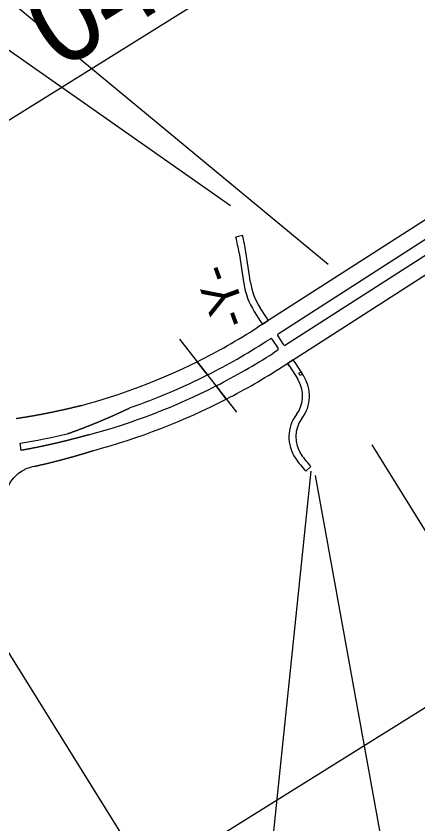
# Model space of a CAD drawing. Extents: x 2038094 to 2053858, y 751760 to 764312.
# Drawn here: x 2046307 to 2046894, y 757655 to 758834 of the extents above; entities that cross this region are included whole.
import ezdxf

# ---------------------------------------------------------------- set-up
doc = ezdxf.new("R2010")
doc.units = 0
for name, color, linetype in [('Default', 7, 'Continuous'), ('Old_Level_14', 7, 'Continuous'), ('Prop Shade Light', 7, 'Continuous'), ('Scratch_Level_1', 7, 'Continuous'), ('Sheet Data Field CELL', 7, 'Continuous')]:
    doc.layers.add(name, color=color, linetype=linetype)

msp = doc.modelspace()

# ---------------------------------------------------------------- linework, layer by layer
at = {"layer": 'Default'}
for p, q in [((2046545.4, 758362.6), (2046628.7, 758255.8)), ((2046595.2, 758298.9), (2046595.2, 758298.9)), ((2046595.2, 758298.9), (2046595.2, 758298.9))]:
    msp.add_line(p, q, dxfattribs=at)
at = {"layer": 'Old_Level_14'}
for points in [[(2046763, 758471.6), (2046248.1, 758896.8), (2045732.1, 758575.3)], [(2046620.1, 758557.1), (2046270.1, 758802), (2045682.1, 758435.8)], [(2046826.6, 758207.9), (2046916.9, 758063.2), (2047239.3, 758264)], [(2046737.4, 758169.4), (2046678.7, 757601.6), (2045930.3, 757135.4)], [(2046743.8, 758163.4), (2046879, 757418.7), (2046051.1, 756903.1)]]:
    msp.add_lwpolyline(points, dxfattribs=at)
at = {"layer": 'Prop Shade Light'}
for p, q in [((2047171.9, 758708.2), (2046658.7, 758379)), ((2046689.7, 758370.3), (2047184.9, 758688)), ((2046999.6, 758545.4), (2046700.5, 758353.5)), ((2046695.4, 758321.8), (2047012.6, 758525.2)), ((2046637.7, 758513.7), (2046627.9, 758511.3)), ((2046632.5, 758488.3), (2046639.5, 758443.4)), ((2046649.3, 758445), (2046642.4, 758489.8)), ((2046672.5, 758393.8), (2046663.2, 758408.3)), ((2046664.1, 758388.4), (2046666.8, 758384.2)), ((2046664.1, 758388.4), (2046666.8, 758384.2)), ((2046666.8, 758384.2), (2046675.2, 758389.6)), ((2046672.5, 758393.8), (2046675.2, 758389.6)), ((2046675.2, 758389.6), (2046672.5, 758393.8)), ((2046698, 758354), (2046689.1, 758367.9)), ((2046671.7, 758358.8), (2046678.3, 758363)), ((2046680.7, 758362.5), (2046689.6, 758348.6)), ((2046689.1, 758346.2), (2046682.5, 758342)), ((2046586.3, 758310.1), (2046571.2, 758329.4)), ((2046571.2, 758329.4), (2046586.3, 758310.1)), ((2046711.9, 758332.3), (2046703.5, 758326.9)), ((2046714.7, 758328.1), (2046711.9, 758332.3)), ((2046714.7, 758328.1), (2046711.9, 758332.3)), ((2046706.2, 758322.8), (2046703.5, 758326.9)), ((2046703.5, 758326.9), (2046706.2, 758322.8)), ((2046706.2, 758322.8), (2046718.4, 758303.8)), ((2046723.3, 758314.7), (2046714.7, 758328.1)), ((2046726.8, 758309.2), (2046723.3, 758314.7)), ((2046613.9, 758274.8), (2046598.9, 758294.1)), ((2046598.9, 758294.1), (2046613.9, 758274.8)), ((2046314, 758200), (2046312.3, 758210.4)), ((2046314, 758200), (2046312.3, 758210.4)), ((2046418.7, 758199.5), (2046418.7, 758199.5)), ((2046730.3, 758169.5), (2046737.6, 758176.4)), ((2046319.1, 758172), (2046318.6, 758171.9)), ((2046319.1, 758172), (2046318.6, 758171.9))]:
    msp.add_line(p, q, dxfattribs=at)
for points in [[(2046654.8, 758402.9), (2046654.8, 758402.9), (2046664.1, 758388.4)], [(2046723.3, 758314.7), (2046725.4, 758311.3), (2046722, 758309.2), (2046719.9, 758312.6), (2046723.3, 758314.7)], [(2046291.3, 758121.3), (2046291.2, 758122.5), (2046290.9, 758125.8), (2046290.8, 758130.1), (2046291, 758133.2), (2046291.8, 758138.8), (2046293.1, 758143), (2046293.8, 758144.8), (2046295.7, 758148.8), (2046297.9, 758152.8), (2046300.2, 758156.4), (2046303, 758159.9), (2046305.1, 758162), (2046307.5, 758164.2), (2046309.6, 758166), (2046312.7, 758168.5), (2046315.5, 758170.1), (2046319.1, 758172)]]:
    msp.add_lwpolyline(points, dxfattribs=at)
for centre, radius, start, end in [((2046341, 758443), 295, 8.8387, 13.4036), ((2046341, 758443), 305, 8.8387, 13.4036), ((2046743.2, 758459.6), 105, 188.8387, 212.6647), ((2046743.2, 758459.6), 95, 188.8387, 212.6814), ((2046164.1, 759150), 916, 296.388, 302.6814), ((2046690.6, 758368.9), 1.75, 122.6814, 212.6814), ((2046164.1, 759150), 940, 296.6881, 302.6814), ((2046679.2, 758361.6), 1.75, 32.6814, 122.6814), ((2046699.5, 758355), 1.75, 212.6814, 302.6814), ((2046164.1, 759150), 960, 296.9266, 302.6814), ((2046688.2, 758347.7), 1.75, 302.6814, 32.6814), ((2046164.1, 759150), 916, 284.9956, 296.388), ((2046164.1, 759150), 984, 297.1997, 302.6814), ((2046164.1, 759150), 940, 289.2174, 296.6881), ((2046680.5, 758279.5), 55, 323.1156, 32.6814), ((2046164.1, 759150), 960, 284.9956, 296.9266), ((2046680.5, 758279.5), 45, 323.1156, 32.6814), ((2046164.1, 759150), 984, 284.9956, 297.1997), ((2046760.5, 758219.5), 55, 143.1156, 214.5162), ((2046760.5, 758219.5), 45, 143.1156, 214.5162), ((2046152.4, 759198.6), 1001, 279.1966, 283.2073), ((2046847, 758279), 160, 214.5162, 223.1771), ((2046847, 758279), 150, 214.5162, 223.1771), ((2046350.9, 758096.8), 81.7, 102.2238, 113.2762)]:
    msp.add_arc(centre, radius, start, end, dxfattribs=at)
for points in [[(2046385.5, 758261.3), (2046385.3, 758261.3), (2046384.7, 758261.1), (2046384, 758261), (2046383.4, 758260.9), (2046382.8, 758260.7), (2046382.1, 758260.6), (2046381.5, 758260.4), (2046380.9, 758260.3), (2046380.2, 758260.1), (2046379.6, 758260), (2046379, 758259.8), (2046378.3, 758259.7), (2046377.7, 758259.5), (2046377.1, 758259.4), (2046376.4, 758259.2), (2046375.8, 758259.1), (2046375.1, 758259), (2046374.5, 758258.8), (2046373.9, 758258.7), (2046373.2, 758258.5), (2046372.6, 758258.4), (2046372, 758258.3), (2046371.3, 758258.1), (2046370.7, 758258), (2046370.1, 758257.8), (2046369.8, 758257.8)], [(2046401.1, 758265.2), (2046399.9, 758264.9), (2046399.2, 758264.7), (2046398.6, 758264.5), (2046398, 758264.4), (2046397.3, 758264.2), (2046396.7, 758264.1), (2046396.1, 758263.9), (2046395.4, 758263.7), (2046394.8, 758263.6), (2046394.2, 758263.4), (2046393.5, 758263.3), (2046392.9, 758263.1), (2046392.3, 758263), (2046391.6, 758262.8), (2046391, 758262.7), (2046390.4, 758262.5), (2046389.7, 758262.4), (2046389.1, 758262.2), (2046388.5, 758262.1), (2046387.8, 758261.9), (2046387.2, 758261.7), (2046386.6, 758261.6), (2046385.9, 758261.4), (2046385.5, 758261.3)], [(2046458.5, 758255.3), (2046458.9, 758255.5), (2046459.5, 758255.8), (2046460.1, 758256.1), (2046460.7, 758256.4), (2046461.3, 758256.6), (2046461.9, 758256.9), (2046462.6, 758257.2), (2046463.2, 758257.5), (2046463.8, 758257.8), (2046464.4, 758258.1), (2046465, 758258.3), (2046465.6, 758258.6), (2046466.2, 758258.9), (2046466.8, 758259.2), (2046467.4, 758259.5), (2046468.1, 758259.8), (2046468.7, 758260.1), (2046469.3, 758260.3), (2046469.9, 758260.6), (2046470.5, 758260.9), (2046471.1, 758261.2), (2046471.7, 758261.5), (2046472.3, 758261.8), (2046473.5, 758262.4)], [(2046322.4, 758248.7), (2046322, 758248.6), (2046321.4, 758248.5), (2046320.7, 758248.4), (2046320.1, 758248.3), (2046319.4, 758248.2), (2046318.8, 758248.1), (2046318.2, 758248), (2046317.5, 758247.9), (2046316.9, 758247.8), (2046316.2, 758247.7), (2046315.6, 758247.6), (2046314.9, 758247.5), (2046314.3, 758247.4), (2046313.6, 758247.3), (2046313, 758247.2), (2046312.4, 758247.1), (2046311.7, 758247), (2046311.1, 758246.9), (2046310.4, 758246.8), (2046309.8, 758246.7), (2046309.1, 758246.6), (2046308.5, 758246.5), (2046307.8, 758246.4), (2046307.2, 758246.3), (2046306.6, 758246.2)], [(2046338.3, 758251.5), (2046338.1, 758251.4), (2046337.4, 758251.3), (2046336.8, 758251.2), (2046336.1, 758251.1), (2046335.5, 758250.9), (2046334.9, 758250.8), (2046334.2, 758250.7), (2046333.6, 758250.6), (2046332.9, 758250.5), (2046332.3, 758250.4), (2046331.7, 758250.3), (2046331, 758250.1), (2046330.4, 758250), (2046329.7, 758249.9), (2046329.1, 758249.8), (2046328.4, 758249.7), (2046327.8, 758249.6), (2046327.2, 758249.5), (2046326.5, 758249.4), (2046325.9, 758249.3), (2046325.2, 758249.2), (2046324.6, 758249), (2046323.9, 758248.9), (2046323.3, 758248.8), (2046322.7, 758248.7), (2046322.4, 758248.7)], [(2046354.1, 758254.5), (2046353.4, 758254.4), (2046352.8, 758254.2), (2046352.2, 758254.1), (2046351.5, 758254), (2046350.9, 758253.9), (2046350.2, 758253.7), (2046349.6, 758253.6), (2046349, 758253.5), (2046348.3, 758253.4), (2046347.7, 758253.2), (2046347, 758253.1), (2046346.4, 758253), (2046345.8, 758252.9), (2046345.1, 758252.7), (2046344.5, 758252.6), (2046343.8, 758252.5), (2046343.2, 758252.4), (2046342.6, 758252.2), (2046341.9, 758252.1), (2046341.3, 758252), (2046340.6, 758251.9), (2046340, 758251.8), (2046339.4, 758251.7), (2046338.7, 758251.5), (2046338.3, 758251.5)], [(2046369.8, 758257.8), (2046369.4, 758257.7), (2046368.8, 758257.6), (2046368.1, 758257.4), (2046367.5, 758257.3), (2046366.9, 758257.1), (2046366.2, 758257), (2046365.6, 758256.9), (2046364.9, 758256.7), (2046364.3, 758256.6), (2046363.7, 758256.5), (2046363, 758256.3), (2046362.4, 758256.2), (2046361.8, 758256.1), (2046361.1, 758255.9), (2046360.5, 758255.8), (2046359.8, 758255.7), (2046359.2, 758255.5), (2046358.6, 758255.4), (2046357.9, 758255.3), (2046357.3, 758255.1), (2046356.6, 758255), (2046356, 758254.9), (2046355.4, 758254.7), (2046354.7, 758254.6), (2046354.1, 758254.5)], [(2046427.9, 758242), (2046428.6, 758242.3), (2046429.2, 758242.6), (2046429.8, 758242.8), (2046430.4, 758243.1), (2046431.1, 758243.3), (2046431.7, 758243.6), (2046432.3, 758243.9), (2046432.9, 758244.1), (2046433.6, 758244.4), (2046434.2, 758244.6), (2046434.8, 758244.9), (2046435.4, 758245.2), (2046436, 758245.4), (2046436.7, 758245.7), (2046437.3, 758246), (2046437.9, 758246.2), (2046438.5, 758246.5), (2046439.1, 758246.8), (2046439.8, 758247), (2046440.4, 758247.3), (2046441, 758247.6), (2046441.6, 758247.8), (2046442.2, 758248.1), (2046442.9, 758248.4), (2046443.3, 758248.5)], [(2046443.3, 758248.5), (2046443.5, 758248.6), (2046444.1, 758248.9), (2046444.7, 758249.2), (2046445.3, 758249.5), (2046446, 758249.7), (2046446.6, 758250), (2046447.2, 758250.3), (2046447.8, 758250.5), (2046448.4, 758250.8), (2046449, 758251.1), (2046449.7, 758251.4), (2046450.3, 758251.6), (2046450.9, 758251.9), (2046451.5, 758252.2), (2046452.1, 758252.5), (2046452.7, 758252.7), (2046453.4, 758253), (2046454, 758253.3), (2046454.6, 758253.6), (2046455.2, 758253.8), (2046455.8, 758254.1), (2046456.4, 758254.4), (2046457, 758254.7), (2046457.7, 758255), (2046458.3, 758255.2), (2046458.5, 758255.3)], [(2046396.8, 758229.8), (2046397, 758229.9), (2046397.7, 758230.1), (2046398.3, 758230.3), (2046398.9, 758230.6), (2046399.6, 758230.8), (2046400.2, 758231.1), (2046400.8, 758231.3), (2046401.5, 758231.5), (2046402.1, 758231.8), (2046402.8, 758232), (2046403.4, 758232.3), (2046404, 758232.5), (2046404.7, 758232.7), (2046405.3, 758233), (2046405.9, 758233.2), (2046406.6, 758233.5), (2046407.2, 758233.7), (2046407.8, 758234), (2046408.4, 758234.2), (2046409.1, 758234.5), (2046409.7, 758234.7), (2046410.3, 758235), (2046411, 758235.2), (2046411.6, 758235.4), (2046412.2, 758235.7), (2046412.4, 758235.8)], [(2046412.4, 758235.8), (2046412.9, 758235.9), (2046413.5, 758236.2), (2046414.1, 758236.4), (2046414.8, 758236.7), (2046415.4, 758236.9), (2046416, 758237.2), (2046416.6, 758237.4), (2046417.3, 758237.7), (2046417.9, 758237.9), (2046418.5, 758238.2), (2046419.2, 758238.4), (2046419.8, 758238.7), (2046420.4, 758239), (2046421, 758239.2), (2046421.7, 758239.5), (2046422.3, 758239.7), (2046422.9, 758240), (2046423.6, 758240.2), (2046424.2, 758240.5), (2046424.8, 758240.7), (2046425.4, 758241), (2046426.1, 758241.3), (2046426.7, 758241.5), (2046427.3, 758241.8), (2046427.9, 758242)], [(2046381.1, 758224.1), (2046381.7, 758224.3), (2046382.3, 758224.5), (2046383, 758224.7), (2046383.6, 758225), (2046384.3, 758225.2), (2046384.9, 758225.4), (2046385.5, 758225.7), (2046386.2, 758225.9), (2046386.8, 758226.1), (2046387.5, 758226.3), (2046388.1, 758226.6), (2046388.7, 758226.8), (2046389.4, 758227), (2046390, 758227.3), (2046390.7, 758227.5), (2046391.3, 758227.7), (2046391.9, 758228), (2046392.6, 758228.2), (2046393.2, 758228.4), (2046393.9, 758228.7), (2046394.5, 758228.9), (2046395.1, 758229.2), (2046395.8, 758229.4), (2046396.4, 758229.6), (2046396.8, 758229.8)], [(2046380, 758214), (2046379.5, 758213.9), (2046378.9, 758213.7), (2046378.2, 758213.6), (2046377.5, 758213.4), (2046376.9, 758213.2), (2046376.2, 758213.1), (2046375.5, 758212.9), (2046374.9, 758212.8), (2046374.2, 758212.6), (2046373.5, 758212.4), (2046372.9, 758212.3), (2046372.2, 758212.1), (2046371.6, 758212), (2046370.9, 758211.8), (2046370.2, 758211.6), (2046369.6, 758211.5), (2046368.9, 758211.3), (2046368.2, 758211.2), (2046367.6, 758211), (2046366.9, 758210.9), (2046366.2, 758210.7), (2046365.6, 758210.5), (2046364.9, 758210.4), (2046364.2, 758210.2), (2046363.6, 758210.1)], [(2046396.3, 758218.2), (2046396.1, 758218.1), (2046395.4, 758218), (2046394.7, 758217.8), (2046394.1, 758217.6), (2046393.4, 758217.4), (2046392.8, 758217.3), (2046392.1, 758217.1), (2046391.4, 758216.9), (2046390.8, 758216.7), (2046390.1, 758216.6), (2046389.4, 758216.4), (2046388.8, 758216.2), (2046388.1, 758216.1), (2046387.5, 758215.9), (2046386.8, 758215.7), (2046386.1, 758215.6), (2046385.5, 758215.4), (2046384.8, 758215.2), (2046384.2, 758215.1), (2046383.5, 758214.9), (2046382.8, 758214.7), (2046382.2, 758214.6), (2046381.5, 758214.4), (2046380.8, 758214.2), (2046380.2, 758214.1), (2046380, 758214)], [(2046412.5, 758222.7), (2046411.2, 758222.3), (2046410.5, 758222.1), (2046409.9, 758221.9), (2046409.2, 758221.7), (2046408.6, 758221.6), (2046407.9, 758221.4), (2046407.3, 758221.2), (2046406.6, 758221), (2046405.9, 758220.8), (2046405.3, 758220.6), (2046404.6, 758220.5), (2046404, 758220.3), (2046403.3, 758220.1), (2046402.7, 758219.9), (2046402, 758219.7), (2046401.3, 758219.6), (2046400.7, 758219.4), (2046400, 758219.2), (2046399.4, 758219), (2046398.7, 758218.8), (2046398, 758218.7), (2046397.4, 758218.5), (2046396.7, 758218.3), (2046396.3, 758218.2)], [(2046330.6, 758203.1), (2046330.2, 758203), (2046329.5, 758202.8), (2046328.8, 758202.7), (2046328.2, 758202.6), (2046327.5, 758202.4), (2046326.8, 758202.3), (2046326.1, 758202.2), (2046325.5, 758202.1), (2046324.8, 758201.9), (2046324.1, 758201.8), (2046323.5, 758201.7), (2046322.8, 758201.6), (2046322.1, 758201.4), (2046321.4, 758201.3), (2046320.8, 758201.2), (2046320.1, 758201.1), (2046319.4, 758200.9), (2046318.7, 758200.8), (2046318.1, 758200.7), (2046317.4, 758200.6), (2046316.7, 758200.4), (2046316.1, 758200.3), (2046315.4, 758200.2), (2046314.7, 758200.1), (2046314, 758200)], [(2046347.1, 758206.4), (2046346.9, 758206.4), (2046346.2, 758206.2), (2046345.6, 758206.1), (2046344.9, 758206), (2046344.2, 758205.8), (2046343.6, 758205.7), (2046342.9, 758205.5), (2046342.2, 758205.4), (2046341.6, 758205.3), (2046340.9, 758205.1), (2046340.2, 758205), (2046339.5, 758204.8), (2046338.9, 758204.7), (2046338.2, 758204.6), (2046337.5, 758204.4), (2046336.9, 758204.3), (2046336.2, 758204.2), (2046335.5, 758204), (2046334.9, 758203.9), (2046334.2, 758203.8), (2046333.5, 758203.6), (2046332.8, 758203.5), (2046332.2, 758203.4), (2046331.5, 758203.2), (2046330.8, 758203.1), (2046330.6, 758203.1)], [(2046363.6, 758210.1), (2046362.9, 758209.9), (2046362.2, 758209.8), (2046361.6, 758209.6), (2046360.9, 758209.5), (2046360.2, 758209.3), (2046359.6, 758209.2), (2046358.9, 758209), (2046358.2, 758208.9), (2046357.6, 758208.7), (2046356.9, 758208.6), (2046356.2, 758208.4), (2046355.6, 758208.3), (2046354.9, 758208.1), (2046354.2, 758208), (2046353.6, 758207.8), (2046352.9, 758207.7), (2046352.2, 758207.5), (2046351.6, 758207.4), (2046350.9, 758207.2), (2046350.2, 758207.1), (2046349.6, 758207), (2046348.9, 758206.8), (2046348.2, 758206.7), (2046347.6, 758206.5), (2046347.1, 758206.4)], [(2046404.7, 758195.2), (2046405.1, 758195.3), (2046405.6, 758195.5), (2046406.2, 758195.6), (2046406.8, 758195.8), (2046407.3, 758196), (2046407.9, 758196.2), (2046408.5, 758196.3), (2046409.1, 758196.5), (2046409.6, 758196.7), (2046410.2, 758196.8), (2046410.8, 758197), (2046411.3, 758197.2), (2046411.9, 758197.4), (2046412.5, 758197.5), (2046413, 758197.7), (2046413.6, 758197.9), (2046414.2, 758198.1), (2046414.7, 758198.2), (2046415.3, 758198.4), (2046415.9, 758198.6), (2046416.5, 758198.8), (2046417, 758199), (2046417.6, 758199.1), (2046418.7, 758199.5)], [(2046376.4, 758187.2), (2046377, 758187.4), (2046377.6, 758187.5), (2046378.1, 758187.7), (2046378.7, 758187.8), (2046379.3, 758188), (2046379.9, 758188.1), (2046380.4, 758188.3), (2046381, 758188.4), (2046381.6, 758188.6), (2046382.2, 758188.8), (2046382.7, 758188.9), (2046383.3, 758189.1), (2046383.9, 758189.2), (2046384.5, 758189.4), (2046385, 758189.5), (2046385.6, 758189.7), (2046386.2, 758189.9), (2046386.8, 758190), (2046387.3, 758190.2), (2046387.9, 758190.3), (2046388.5, 758190.5), (2046389, 758190.7), (2046389.6, 758190.8), (2046390.2, 758191), (2046390.6, 758191.1)], [(2046390.6, 758191.1), (2046390.8, 758191.1), (2046391.3, 758191.3), (2046391.9, 758191.5), (2046392.5, 758191.6), (2046393.1, 758191.8), (2046393.6, 758192), (2046394.2, 758192.1), (2046394.8, 758192.3), (2046395.3, 758192.5), (2046395.9, 758192.6), (2046396.5, 758192.8), (2046397.1, 758192.9), (2046397.6, 758193.1), (2046398.2, 758193.3), (2046398.8, 758193.4), (2046399.3, 758193.6), (2046399.9, 758193.8), (2046400.5, 758193.9), (2046401.1, 758194.1), (2046401.6, 758194.3), (2046402.2, 758194.5), (2046402.8, 758194.6), (2046403.3, 758194.8), (2046403.9, 758195), (2046404.5, 758195.1), (2046404.7, 758195.2)], [(2046333.6, 758176.7), (2046334.2, 758176.9), (2046334.7, 758177), (2046335.3, 758177.1), (2046335.9, 758177.2), (2046336.5, 758177.4), (2046337.1, 758177.5), (2046337.6, 758177.6), (2046338.2, 758177.8), (2046338.8, 758177.9), (2046339.4, 758178), (2046340, 758178.2), (2046340.6, 758178.3), (2046341.1, 758178.4), (2046341.7, 758178.6), (2046342.3, 758178.7), (2046342.9, 758178.8), (2046343.5, 758179), (2046344, 758179.1), (2046344.6, 758179.2), (2046345.2, 758179.4), (2046345.8, 758179.5), (2046346.4, 758179.6), (2046346.9, 758179.8), (2046347.5, 758179.9), (2046347.9, 758180)], [(2046347.9, 758180), (2046348.1, 758180.1), (2046348.7, 758180.2), (2046349.3, 758180.3), (2046349.8, 758180.5), (2046350.4, 758180.6), (2046351, 758180.8), (2046351.6, 758180.9), (2046352.2, 758181), (2046352.7, 758181.2), (2046353.3, 758181.3), (2046353.9, 758181.5), (2046354.5, 758181.6), (2046355.1, 758181.7), (2046355.6, 758181.9), (2046356.2, 758182), (2046356.8, 758182.2), (2046357.4, 758182.3), (2046357.9, 758182.4), (2046358.5, 758182.6), (2046359.1, 758182.7), (2046359.7, 758182.9), (2046360.3, 758183), (2046360.8, 758183.2), (2046361.4, 758183.3), (2046362, 758183.5), (2046362.2, 758183.5)], [(2046362.2, 758183.5), (2046362.6, 758183.6), (2046363.2, 758183.7), (2046363.7, 758183.9), (2046364.3, 758184), (2046364.9, 758184.2), (2046365.5, 758184.3), (2046366, 758184.5), (2046366.6, 758184.6), (2046367.2, 758184.8), (2046367.8, 758184.9), (2046368.3, 758185.1), (2046368.9, 758185.2), (2046369.5, 758185.4), (2046370.1, 758185.5), (2046370.7, 758185.7), (2046371.2, 758185.8), (2046371.8, 758186), (2046372.4, 758186.1), (2046373, 758186.3), (2046373.5, 758186.4), (2046374.1, 758186.6), (2046374.7, 758186.7), (2046375.3, 758186.9), (2046375.8, 758187), (2046376.4, 758187.2)]]:
    msp.add_spline(points, degree=3, dxfattribs=at)
at = {"layer": 'Scratch_Level_1'}
msp.add_lwpolyline([(2045946.3, 758464.5), (2046501.4, 757573.2), (2047629.6, 758276), (2047220.5, 759009), (2047136.3, 758956.5), (2047077, 759051.7), (2046934.2, 758962.7), (2046881.6, 759047.1)], close=True, dxfattribs=at)

# ---------------------------------------------------------------- texts
msp.add_text('04', height=125, rotation=31.918, dxfattribs=at).set_placement((2046370.6, 758753.1))
at = {"layer": 'Sheet Data Field CELL'}
msp.add_text('-Y-', height=52.5, rotation=110.1466, dxfattribs=at).set_placement((2046648.3, 758388.8))

doc.saveas('drawing.dxf')
